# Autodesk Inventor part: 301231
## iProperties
Created: 2007-11
Part Number: 301231
Document SubType Name: Modeling
Designer: TH
Density: 7.85 g/cm^3
Mass: 265.869 g
Surface Area: 247.179 cm^2
Volume: 33.8686 cm^3
Material: Steel
Description: RIGHT SIDE SPRING BACKET
Component Category: Back Component
Author: TH
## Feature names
1. Extrusion1
2. Extrusion3
3. Fillet2
4. Fillet3
5. Extrusion4
6. Fillet4
7. Fillet5
8. Fillet6
9. Fillet7
10. Shell1
11. Fillet8
12. Extrusion5
13. Extrusion6
14. Fillet9
15. Fillet10
16. Extrusion7
17. Extrusion8
18. Extrusion9
19. Extrusion10
20. Extrusion11
21. Fillet11
22. Extrusion12
23. Extrusion13
24. Fillet14
25. Fillet12
26. Fillet15
27. Extrusion14
28. Hole1
29. Extrusion15
30. Extrusion16
31. Fillet16
32. Fillet17
33. Fillet18
